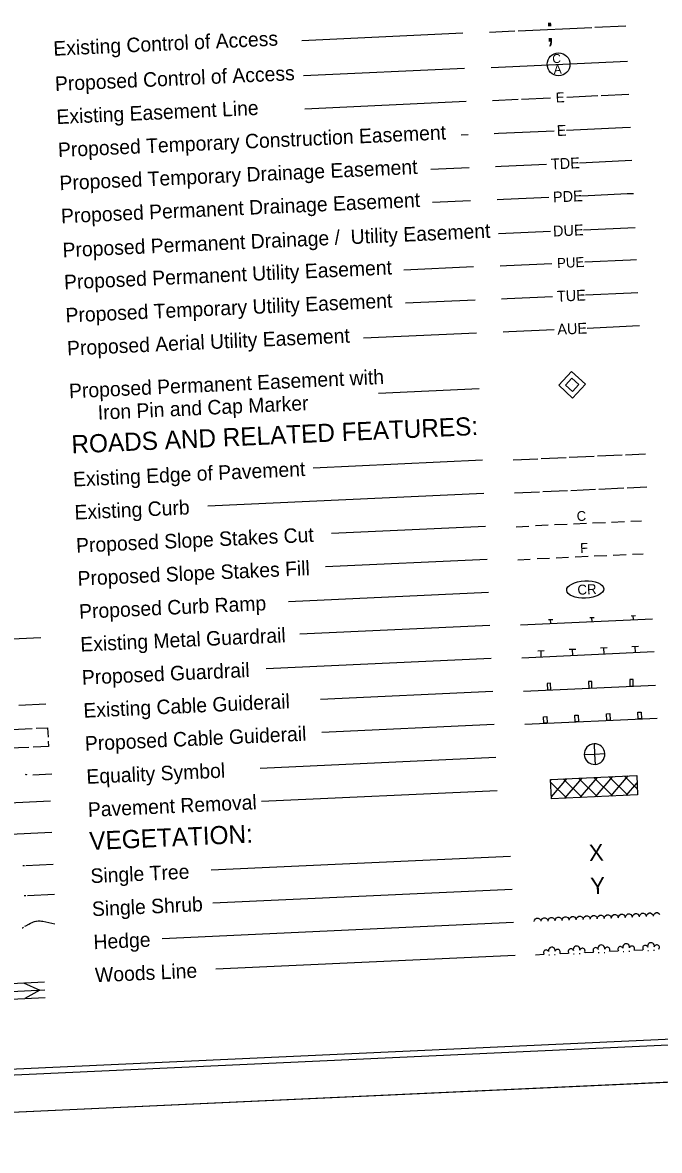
# Model space of a CAD drawing. Extents: x 1190067 to 1192950, y 891516 to 893460.
# Drawn here: x 1191359.1 to 1191513.1, y 891516.5 to 891789.2 of the extents above; entities that cross this region are included whole.
import ezdxf

# ---------------------------------------------------------------- set-up
doc = ezdxf.new("R2010")
doc.units = 0
for name, color, linetype in [('Prop Dimension Text', 7, 'Continuous'), ('Prop Easement Permanent Drainage Utility', 7, 'Continuous'), ('Prop ROW Permanent Easement CELL', 7, 'Continuous'), ('Prop WCC CELL', 7, 'Continuous'), ('Sheet Cutting Line CELL', 7, 'Continuous'), ('Sheet Plot Border Inside CELL', 7, 'Continuous'), ('Sheet Plot Border Outside CELL', 7, 'Continuous'), ('Sheet Symbology CELL', 7, 'Continuous')]:
    doc.layers.add(name, color=color, linetype=linetype)

# ---------------------------------------------------------------- blocks, each defined once
blk = doc.blocks.new('EQCIR')
at = {"layer": 'Sheet Symbology CELL'}
for p, q in [((-0.25, 0), (0, 0)), ((0, 0.25), (0, 0)), ((0, 0), (0, -0.25)), ((0, 0), (0.25, 0))]:
    blk.add_line(p, q, dxfattribs=at)
for start, end in [(89.9944, 179.9989), (359.9944, 89.9989), (179.9944, 269.9989), (269.9944, 359.9989)]:
    blk.add_arc((0, 0), 0.25, start, end, dxfattribs=at)
blk = doc.blocks.new('ROW Marker Permanent Easement-E')
at = {"layer": 'Prop ROW Permanent Easement CELL'}
blk.add_line((0, 0), (0, 0), dxfattribs=at)
for points in [[(0, 0.072), (0.072, 0), (0, -0.072), (-0.072, 0)], [(0, 0.036), (0.036, 0), (0, -0.036), (-0.036, 0)]]:
    blk.add_lwpolyline(points, close=True, dxfattribs=at)
blk = doc.blocks.new('CR')
at = {"layer": 'Prop WCC CELL'}
blk.add_ellipse((0.02, -0.02), major_axis=(5.61, 0), ratio=0.462467, dxfattribs=at)
blk.add_text('CR', height=3, dxfattribs=at).set_placement((-2.34, -1.5))

msp = doc.modelspace()

# ---------------------------------------------------------------- linework, layer by layer
at = {"layer": 'Prop Easement Permanent Drainage Utility'}
for p, q in [((1191474.24, 891738.12), (1191486.75, 891738.7)), ((1191494.74, 891739.06), (1191507.21, 891739.63))]:
    msp.add_line(p, q, dxfattribs=at)
at = {"layer": 'Sheet Cutting Line CELL'}
msp.add_line((1191153.84, 891516.49), (1191826.73, 891547.27), dxfattribs=at)
at = {"layer": 'Sheet Plot Border Inside CELL'}
msp.add_lwpolyline([(1191158.62, 891525.69), (1191824.52, 891556.16), (1191805.24, 891977.76), (1191139.33, 891947.29)], close=True, dxfattribs=at)
at = {"layer": 'Sheet Plot Border Outside CELL'}
msp.add_lwpolyline([(1191153.84, 891516.49), (1191826.73, 891547.27), (1191806.62, 891986.81), (1191133.73, 891956.03)], close=True, dxfattribs=at)
at = {"layer": 'Sheet Symbology CELL'}
for p, q in [((1191478.99, 891787.17), (1191496.74, 891787.98)), ((1191497.53, 891788.01), (1191504.98, 891788.35)), ((1191465.61, 891786.55), (1191426.63, 891784.77)), ((1191472.01, 891786.85), (1191478.19, 891787.13)), ((1191472.4, 891778.31), (1191505.37, 891779.82)), ((1191466, 891778.02), (1191427.02, 891776.24)), ((1191490.75, 891771.15), (1191498.25, 891771.49)), ((1191499.05, 891771.53), (1191505.73, 891771.83)), ((1191466.36, 891770.03), (1191427.38, 891768.25)), ((1191472.77, 891770.32), (1191478.97, 891770.61)), ((1191479.77, 891770.64), (1191486.76, 891770.96)), ((1191474.18, 891762.38), (1191487.66, 891763)), ((1191490.66, 891763.13), (1191504.15, 891763.75)), ((1191504.15, 891763.75), (1191506.1, 891763.84)), ((1191466.88, 891762.05), (1191465.21, 891761.97)), ((1191473.13, 891762.33), (1191474.18, 891762.38)), ((1191474.84, 891754.4), (1191485.83, 891754.9)), ((1191493.82, 891755.27), (1191504.81, 891755.77)), ((1191504.81, 891755.77), (1191506.46, 891755.85)), ((1191467.09, 891754.05), (1191457.84, 891753.62)), ((1191473.5, 891754.34), (1191474.84, 891754.4)), ((1191475.38, 891746.42), (1191486.37, 891746.92)), ((1191494.36, 891747.29), (1191505.35, 891747.79)), ((1191505.35, 891747.79), (1191506.83, 891747.86)), ((1191467.46, 891746.06), (1191458.21, 891745.63)), ((1191473.86, 891746.35), (1191475.38, 891746.42)), ((1191474.6, 891730.36), (1191476.13, 891730.43)), ((1191476.13, 891730.43), (1191487.12, 891730.93)), ((1191495.11, 891731.3), (1191506.1, 891731.8)), ((1191506.1, 891731.8), (1191507.56, 891731.87)), ((1191468.19, 891730.07), (1191451.35, 891729.3)), ((1191468.56, 891722.08), (1191451.72, 891721.31)), ((1191474.96, 891722.37), (1191476.3, 891722.43)), ((1191476.3, 891722.43), (1191487.29, 891722.93)), ((1191495.28, 891723.3), (1191506.27, 891723.8)), ((1191506.27, 891723.8), (1191507.93, 891723.88)), ((1191468.92, 891714.09), (1191441.57, 891712.83)), ((1191475.33, 891714.38), (1191476.67, 891714.44)), ((1191476.67, 891714.44), (1191487.65, 891714.94)), ((1191495.65, 891715.31), (1191506.63, 891715.81)), ((1191506.63, 891715.81), (1191508.29, 891715.89)), ((1191469.54, 891700.57), (1191445.16, 891699.45)), ((1191484.54, 891683.75), (1191490.53, 891684.02)), ((1191491.33, 891684.06), (1191497.32, 891684.33)), ((1191498.12, 891684.37), (1191504.12, 891684.64)), ((1191504.92, 891684.68), (1191509.71, 891684.9)), ((1191470.33, 891683.33), (1191429.43, 891681.45)), ((1191477.74, 891683.43), (1191483.74, 891683.71)), ((1191478.11, 891675.44), (1191484.1, 891675.72)), ((1191484.9, 891675.75), (1191490.9, 891676.03)), ((1191491.7, 891676.06), (1191497.69, 891676.34)), ((1191498.49, 891676.38), (1191504.48, 891676.65)), ((1191505.28, 891676.69), (1191510.08, 891676.91)), ((1191470.69, 891675.33), (1191403.9, 891672.28)), ((1191486.2, 891667.61), (1191483.18, 891667.48)), ((1191490.79, 891667.82), (1191487.75, 891667.69)), ((1191495.49, 891668.04), (1191492.37, 891667.9)), ((1191500.06, 891668.25), (1191496.96, 891668.11)), ((1191504.68, 891668.46), (1191501.54, 891668.32)), ((1191508.79, 891668.65), (1191506.23, 891668.53)), ((1191471.06, 891667.34), (1191433.82, 891665.64)), ((1191478.48, 891667.26), (1191481.52, 891667.4)), ((1191471.43, 891659.35), (1191432.37, 891657.56)), ((1191478.85, 891659.27), (1191481.89, 891659.41)), ((1191486.56, 891659.62), (1191483.54, 891659.48)), ((1191491.16, 891659.83), (1191488.12, 891659.69)), ((1191495.85, 891660.05), (1191492.73, 891659.9)), ((1191500.43, 891660.26), (1191497.33, 891660.12)), ((1191505.04, 891660.47), (1191501.91, 891660.32)), ((1191509.16, 891660.66), (1191506.6, 891660.54)), ((1191471.79, 891651.36), (1191423.47, 891649.15)), ((1191506.29, 891645.75), (1191507.29, 891645.79)), ((1191506.83, 891644.77), (1191506.79, 891645.77)), ((1191472.09, 891643.41), (1191426.21, 891641.31)), ((1191479.51, 891643.52), (1191511.47, 891644.98)), ((1191486.31, 891644.83), (1191487.31, 891644.88)), ((1191486.85, 891643.86), (1191486.81, 891644.86)), ((1191496.3, 891645.29), (1191497.3, 891645.34)), ((1191496.84, 891644.31), (1191496.8, 891645.31)), ((1191331.62, 891639), (1191363.58, 891640.46)), ((1191491.28, 891637.63), (1191492.88, 891637.71)), ((1191492.15, 891636.09), (1191492.08, 891637.67)), ((1191498.87, 891637.98), (1191500.47, 891638.05)), ((1191499.74, 891636.44), (1191499.67, 891638.02)), ((1191506.46, 891638.33), (1191508.06, 891638.4)), ((1191507.33, 891636.79), (1191507.26, 891638.36)), ((1191472.46, 891635.42), (1191418.02, 891632.93)), ((1191511.84, 891636.99), (1191479.87, 891635.53)), ((1191483.69, 891637.29), (1191485.28, 891637.36)), ((1191484.56, 891635.74), (1191484.49, 891637.32)), ((1191472.82, 891627.43), (1191431.15, 891625.52)), ((1191480.24, 891627.54), (1191512.2, 891629)), ((1191358.19, 891624.12), (1191364.77, 891624.42)), ((1191356.47, 891618.27), (1191361.47, 891618.5)), ((1191473.19, 891619.44), (1191431.51, 891617.53)), ((1191480.6, 891619.55), (1191512.57, 891621.01)), ((1191360.66, 891613.93), (1191355.67, 891613.7)), ((1191473.55, 891611.45), (1191416.56, 891608.84)), ((1191486.8, 891606.16), (1191507.62, 891607.11)), ((1191487.02, 891601.49), (1191486.8, 891606.16)), ((1191486.81, 891605.92), (1191487.02, 891606.17)), ((1191490.71, 891601.65), (1191486.84, 891605.44)), ((1191487, 891601.95), (1191490.74, 891606.34)), ((1191494.43, 891601.82), (1191489.82, 891606.3)), ((1191490.27, 891601.63), (1191494.45, 891606.51)), ((1191498.12, 891601.99), (1191493.54, 891606.47)), ((1191493.97, 891601.8), (1191498.17, 891606.68)), ((1191501.84, 891602.16), (1191497.23, 891606.64)), ((1191497.68, 891601.97), (1191501.87, 891606.85)), ((1191505.56, 891602.33), (1191500.93, 891606.81)), ((1191501.4, 891602.14), (1191505.56, 891607.02)), ((1191507.77, 891603.94), (1191504.64, 891606.98)), ((1191505.1, 891602.31), (1191507.7, 891605.35)), ((1191507.62, 891607.11), (1191507.83, 891602.44)), ((1191473.92, 891603.45), (1191416.93, 891600.85)), ((1191507.83, 891602.44), (1191487.02, 891601.49)), ((1191365.85, 891600.94), (1191354.14, 891600.4)), ((1191366.19, 891593.35), (1191354.48, 891592.82)), ((1191359.96, 891585.38), (1191366.55, 891585.68)), ((1191477.11, 891587.56), (1191404.73, 891584.24)), ((1191359.16, 891585.35), (1191359.56, 891585.36)), ((1191359.49, 891578.11), (1191359.89, 891578.12)), ((1191360.29, 891578.14), (1191366.88, 891578.44)), ((1191477.47, 891579.56), (1191405.1, 891576.25)), ((1191482.79, 891571.8), (1191482.89, 891572.18)), ((1191482.89, 891572.18), (1191483.12, 891572.45)), ((1191483.12, 891572.45), (1191483.43, 891572.65)), ((1191483.43, 891572.65), (1191483.81, 891572.67)), ((1191483.81, 891572.67), (1191484.14, 891572.48)), ((1191484.14, 891572.48), (1191484.37, 891572.23)), ((1191484.37, 891572.23), (1191484.47, 891571.9)), ((1191484.49, 891571.88), (1191484.59, 891572.26)), ((1191484.59, 891572.26), (1191484.82, 891572.53)), ((1191484.82, 891572.53), (1191485.13, 891572.73)), ((1191485.13, 891572.73), (1191485.51, 891572.74)), ((1191485.51, 891572.74), (1191485.84, 891572.56)), ((1191485.84, 891572.56), (1191486.07, 891572.31)), ((1191486.07, 891572.31), (1191486.16, 891571.97)), ((1191486.18, 891571.95), (1191486.29, 891572.34)), ((1191486.29, 891572.34), (1191486.52, 891572.61)), ((1191486.52, 891572.61), (1191486.83, 891572.8)), ((1191486.83, 891572.8), (1191487.21, 891572.82)), ((1191487.21, 891572.82), (1191487.54, 891572.64)), ((1191487.54, 891572.64), (1191487.77, 891572.39)), ((1191487.77, 891572.39), (1191487.86, 891572.05)), ((1191487.88, 891572.03), (1191487.99, 891572.42)), ((1191487.99, 891572.42), (1191488.21, 891572.69)), ((1191488.21, 891572.69), (1191488.52, 891572.88)), ((1191488.52, 891572.88), (1191488.9, 891572.9)), ((1191488.9, 891572.9), (1191489.23, 891572.71)), ((1191489.23, 891572.71), (1191489.47, 891572.46)), ((1191489.47, 891572.46), (1191489.56, 891572.13)), ((1191489.58, 891572.11), (1191489.68, 891572.49)), ((1191489.68, 891572.49), (1191489.91, 891572.77)), ((1191489.91, 891572.77), (1191490.22, 891572.96)), ((1191490.22, 891572.96), (1191490.6, 891572.98)), ((1191490.6, 891572.98), (1191490.93, 891572.79)), ((1191490.93, 891572.79), (1191491.16, 891572.54)), ((1191491.16, 891572.54), (1191491.26, 891572.21)), ((1191491.28, 891572.19), (1191491.38, 891572.57)), ((1191491.38, 891572.57), (1191491.61, 891572.84)), ((1191491.61, 891572.84), (1191491.92, 891573.04)), ((1191491.92, 891573.04), (1191492.3, 891573.05)), ((1191492.3, 891573.05), (1191492.63, 891572.87)), ((1191492.63, 891572.87), (1191492.86, 891572.62)), ((1191492.86, 891572.62), (1191492.96, 891572.28)), ((1191492.98, 891572.26), (1191493.08, 891572.65)), ((1191493.08, 891572.65), (1191493.31, 891572.92)), ((1191493.31, 891572.92), (1191493.62, 891573.11)), ((1191493.62, 891573.11), (1191494, 891573.13)), ((1191494, 891573.13), (1191494.33, 891572.95)), ((1191494.33, 891572.95), (1191494.56, 891572.7)), ((1191494.56, 891572.7), (1191494.66, 891572.36)), ((1191494.68, 891572.34), (1191494.78, 891572.73)), ((1191494.78, 891572.73), (1191495.01, 891573)), ((1191495.01, 891573), (1191495.32, 891573.19)), ((1191495.32, 891573.19), (1191495.7, 891573.21)), ((1191495.7, 891573.21), (1191496.03, 891573.02)), ((1191496.03, 891573.02), (1191496.26, 891572.78)), ((1191496.26, 891572.78), (1191496.35, 891572.44)), ((1191496.37, 891572.42), (1191496.48, 891572.81)), ((1191496.48, 891572.81), (1191496.7, 891573.08)), ((1191496.7, 891573.08), (1191497.02, 891573.27)), ((1191497.02, 891573.27), (1191497.4, 891573.29)), ((1191497.4, 891573.29), (1191497.72, 891573.1)), ((1191497.72, 891573.1), (1191497.96, 891572.85)), ((1191497.96, 891572.85), (1191498.05, 891572.52)), ((1191498.07, 891572.5), (1191498.18, 891572.88)), ((1191498.18, 891572.88), (1191498.4, 891573.15)), ((1191498.4, 891573.15), (1191498.71, 891573.35)), ((1191498.71, 891573.35), (1191499.09, 891573.37)), ((1191499.09, 891573.37), (1191499.42, 891573.18)), ((1191499.42, 891573.18), (1191499.65, 891572.93)), ((1191499.65, 891572.93), (1191499.75, 891572.59)), ((1191499.77, 891572.58), (1191499.87, 891572.96)), ((1191499.87, 891572.96), (1191500.1, 891573.23)), ((1191500.1, 891573.23), (1191500.41, 891573.43)), ((1191500.41, 891573.43), (1191500.79, 891573.44)), ((1191500.79, 891573.44), (1191501.12, 891573.26)), ((1191501.12, 891573.26), (1191501.35, 891573.01)), ((1191501.35, 891573.01), (1191501.45, 891572.67)), ((1191501.47, 891572.65), (1191501.57, 891573.04)), ((1191501.57, 891573.04), (1191501.8, 891573.31)), ((1191501.8, 891573.31), (1191502.11, 891573.5)), ((1191502.11, 891573.5), (1191502.49, 891573.52)), ((1191502.49, 891573.52), (1191502.82, 891573.34)), ((1191502.82, 891573.34), (1191503.05, 891573.09)), ((1191503.05, 891573.09), (1191503.15, 891572.75)), ((1191503.17, 891572.73), (1191503.27, 891573.12)), ((1191503.27, 891573.12), (1191503.5, 891573.39)), ((1191503.5, 891573.39), (1191503.81, 891573.58)), ((1191503.81, 891573.58), (1191504.19, 891573.6)), ((1191504.19, 891573.6), (1191504.52, 891573.41)), ((1191504.52, 891573.41), (1191504.75, 891573.16)), ((1191504.75, 891573.16), (1191504.84, 891572.83)), ((1191504.87, 891572.81), (1191504.97, 891573.19)), ((1191504.97, 891573.19), (1191505.2, 891573.46)), ((1191505.2, 891573.46), (1191505.51, 891573.66)), ((1191505.51, 891573.66), (1191505.89, 891573.68)), ((1191505.89, 891573.68), (1191506.22, 891573.49)), ((1191506.22, 891573.49), (1191506.45, 891573.24)), ((1191506.45, 891573.24), (1191506.54, 891572.91)), ((1191506.56, 891572.89), (1191506.67, 891573.27)), ((1191506.67, 891573.27), (1191506.89, 891573.54)), ((1191506.89, 891573.54), (1191507.21, 891573.74)), ((1191507.21, 891573.74), (1191507.59, 891573.75)), ((1191507.59, 891573.75), (1191507.91, 891573.57)), ((1191507.91, 891573.57), (1191508.15, 891573.32)), ((1191508.15, 891573.32), (1191508.24, 891572.98)), ((1191508.26, 891572.96), (1191508.36, 891573.35)), ((1191508.36, 891573.35), (1191508.59, 891573.62)), ((1191508.59, 891573.62), (1191508.9, 891573.81)), ((1191508.9, 891573.81), (1191509.28, 891573.83)), ((1191509.28, 891573.83), (1191509.61, 891573.65)), ((1191509.61, 891573.65), (1191509.84, 891573.4)), ((1191509.84, 891573.4), (1191509.94, 891573.06)), ((1191509.96, 891573.04), (1191510.06, 891573.43)), ((1191510.06, 891573.43), (1191510.29, 891573.7)), ((1191510.29, 891573.7), (1191510.6, 891573.89)), ((1191510.6, 891573.89), (1191510.98, 891573.91)), ((1191510.98, 891573.91), (1191511.31, 891573.72)), ((1191511.31, 891573.72), (1191511.54, 891573.47)), ((1191511.54, 891573.47), (1191511.64, 891573.14)), ((1191511.66, 891573.12), (1191511.76, 891573.5)), ((1191511.76, 891573.5), (1191511.99, 891573.78)), ((1191511.99, 891573.78), (1191512.3, 891573.97)), ((1191512.3, 891573.97), (1191512.68, 891573.99)), ((1191512.68, 891573.99), (1191513.01, 891573.8)), ((1191513.01, 891573.8), (1191513.24, 891573.55)), ((1191477.84, 891571.57), (1191392.85, 891567.68)), ((1191483.15, 891563.81), (1191485.15, 891563.9)), ((1191489.15, 891564.08), (1191491.15, 891564.17)), ((1191492.33, 891564.03), (1191492.53, 891564.04)), ((1191493.73, 891564.09), (1191493.93, 891564.1)), ((1191495.14, 891564.36), (1191497.14, 891564.45)), ((1191498.33, 891564.3), (1191498.53, 891564.31)), ((1191499.73, 891564.36), (1191499.93, 891564.37)), ((1191501.14, 891564.63), (1191503.13, 891564.72)), ((1191504.32, 891564.58), (1191504.52, 891564.58)), ((1191505.72, 891564.64), (1191505.92, 891564.65)), ((1191507.13, 891564.9), (1191509.13, 891565)), ((1191510.31, 891564.85), (1191510.51, 891564.86)), ((1191511.71, 891564.91), (1191511.91, 891564.92)), ((1191478.2, 891563.58), (1191405.83, 891560.27)), ((1191486.34, 891563.75), (1191486.54, 891563.76)), ((1191487.74, 891563.82), (1191487.94, 891563.83)), ((1191340.06, 891556.09), (1191364.44, 891557.21)), ((1191359.36, 891556.98), (1191363.28, 891555.23)), ((1191340.04, 891554.17), (1191364.53, 891555.29)), ((1191340.23, 891552.32), (1191364.61, 891553.43)), ((1191363.28, 891555.23), (1191359.64, 891553.21))]:
    msp.add_line(p, q, dxfattribs=at)
for points in [[(1191800.29, 891976.51), (1191200.91, 891949.09), (1191220.09, 891529.94), (1191819.46, 891557.36)], [(1191486.02, 891627.8), (1191486.82, 891627.84), (1191486.75, 891629.44), (1191485.95, 891629.4)], [(1191496.01, 891628.26), (1191496.81, 891628.3), (1191496.74, 891629.89), (1191495.94, 891629.86)], [(1191506, 891628.72), (1191506.8, 891628.75), (1191506.73, 891630.35), (1191505.93, 891630.31)], [(1191485.11, 891621.35), (1191485.91, 891621.39), (1191485.98, 891619.79), (1191485.18, 891619.76)], [(1191492.7, 891621.7), (1191493.5, 891621.74), (1191493.58, 891620.14), (1191492.78, 891620.1)], [(1191500.3, 891622.05), (1191501.09, 891622.09), (1191501.17, 891620.49), (1191500.37, 891620.45)], [(1191507.89, 891622.4), (1191508.69, 891622.43), (1191508.76, 891620.83), (1191507.96, 891620.8)]]:
    msp.add_lwpolyline(points, close=True, dxfattribs=at)
for points in [[(1191362.46, 891618.54), (1191365.19, 891618.67), (1191365.3, 891616.4)], [(1191365.34, 891615.4), (1191365.4, 891614.14), (1191361.66, 891613.97)], [(1191361.64, 891607.3), (1191366.2, 891607.51)], [(1191359.01, 891570.29), (1191359.08, 891570.33), (1191359.36, 891570.47)], [(1191359.71, 891570.67), (1191359.9, 891570.77), (1191360.67, 891571.22), (1191361.06, 891571.43), (1191361.46, 891571.62), (1191361.77, 891571.74), (1191362.05, 891571.82), (1191362.3, 891571.88), (1191362.52, 891571.93), (1191362.9, 891571.97), (1191363.19, 891571.98), (1191363.41, 891571.98), (1191363.73, 891571.95), (1191364.05, 891571.89), (1191365.48, 891571.57), (1191366.92, 891571.24)]]:
    msp.add_lwpolyline(points, dxfattribs=at)
msp.add_circle((1191488.73, 891779.06), 2.76, dxfattribs=at)
for centre, radius, start, end in [((1191511.07, 891565.89), 0.825, 348.5832, 196.6557), ((1191485.71, 891564.33), 0.632, 21.0544, 221.851), ((1191487.09, 891564.79), 0.825, 348.5832, 196.6557), ((1191488.51, 891564.46), 0.632, 323.3879, 164.1845), ((1191491.71, 891564.6), 0.632, 21.0544, 221.851), ((1191493.09, 891565.07), 0.825, 348.5832, 196.6557), ((1191494.5, 891564.73), 0.632, 323.3879, 164.1845), ((1191497.7, 891564.88), 0.632, 21.0544, 221.851), ((1191499.08, 891565.34), 0.825, 348.5832, 196.6557), ((1191500.5, 891565.01), 0.632, 323.3879, 164.1845), ((1191503.69, 891565.15), 0.632, 21.0544, 221.851), ((1191505.07, 891565.62), 0.825, 348.5832, 196.6557), ((1191506.49, 891565.28), 0.632, 323.3879, 164.1845), ((1191509.69, 891565.43), 0.632, 21.0544, 221.851), ((1191512.48, 891565.56), 0.632, 323.3879, 164.1845)]:
    msp.add_arc(centre, radius, start, end, dxfattribs=at)
msp.add_ellipse((1191359.99, 891607.34), major_axis=(-0.0036, 0.0787), ratio=0.938496, dxfattribs=at)

# ---------------------------------------------------------------- block references
at = {"layer": 'Prop Dimension Text'}
for name, p, xscale, yscale, rotation in [('ROW Marker Permanent Easement-E', (1191491.99, 891701.6), 44.73509307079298, 44.73509307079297, 2.6194666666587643), ('CR', (1191495.16, 891652.1), 0.8000000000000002, 0.7999999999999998, 2.6194666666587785), ('EQCIR', (1191497.44, 891612.3), 10.000000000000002, 10, 2.619466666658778)]:
    msp.add_blockref(name, p, dxfattribs=dict(at, xscale=xscale, yscale=yscale, rotation=rotation))

# ---------------------------------------------------------------- texts
at = {"layer": 'Prop Easement Permanent Drainage Utility'}
msp.add_text('DUE', height=2.62, rotation=2.6195, dxfattribs=at).set_placement((1191487.44, 891737.41))
at = {"layer": 'Sheet Symbology CELL'}
for s, height, p in [(';', 6, (1191485.63, 891784.47)), ('Existing Control of Access', 3.5, (1191366.65, 891781.12)), ('C', 2.16, (1191487.26, 891779.32)), ('Proposed Control of Access', 3.5, (1191367.04, 891772.59)), ('A', 2.16, (1191487.59, 891776.74)), ('E', 2.4, (1191488.09, 891769.82)), ('Existing Easement Line', 3.5, (1191367.41, 891764.6)), ('Proposed Temporary Construction Easement', 3.5, (1191367.77, 891756.61)), ('E', 2.62, (1191488.36, 891761.71)), ('Proposed Temporary Drainage Easement', 3.5, (1191368.14, 891748.61)), ('TDE', 2.62, (1191486.93, 891753.63)), ('Proposed Permanent Drainage Easement', 3.5, (1191368.5, 891740.62)), ('PDE', 2.62, (1191487.43, 891745.65)), ('Proposed Permanent Drainage /  Utility Easement', 3.5, (1191368.88, 891732.4)), ('Proposed Permanent Utility Easement', 3.5, (1191369.24, 891724.64)), ('PUE', 2.4, (1191488.41, 891729.79)), ('Proposed Temporary Utility Easement', 3.5, (1191369.6, 891716.64)), ('TUE', 2.62, (1191488.38, 891721.66)), ('AUE', 2.62, (1191488.48, 891713.66)), ('Proposed Aerial Utility Easement', 3.5, (1191369.97, 891708.65)), ('Proposed Permanent Easement with', 3.5, (1191370.44, 891698.32)), ('Iron Pin and Cap Marker', 3.5, (1191377.39, 891693.13)), ('ROADS AND RELATED FEATURES:', 4.4, (1191371.05, 891684.97)), ('Existing Edge of Pavement', 3.5, (1191371.42, 891676.98)), ('Existing Curb', 3.5, (1191371.78, 891668.99)), ('C', 2.37, (1191493.16, 891668.63)), ('Proposed Slope Stakes Cut', 3.5, (1191372.15, 891660.99)), ('F', 2.37, (1191493.99, 891660.91)), ('Proposed Slope Stakes Fill', 3.5, (1191372.51, 891653)), ('Proposed Curb Ramp', 3.5, (1191372.88, 891645.01)), ('Existing Metal Guardrail', 3.5, (1191373.18, 891637.07)), ('Proposed Guardrail', 3.5, (1191373.55, 891629.08)), ('Existing Cable Guiderail', 3.5, (1191373.92, 891621.09)), ('Proposed Cable Guiderail', 3.5, (1191374.28, 891613.1)), ('Equality Symbol', 3.5, (1191374.65, 891605.1)), ('Pavement Removal', 3.5, (1191375.01, 891597.11)), ('VEGETATION:', 4.4, (1191375.37, 891589.09)), ('X', 4, (1191496.13, 891586.42)), ('Single Tree', 3.5, (1191375.63, 891581.1)), ('Y', 4, (1191496.5, 891578.43)), ('Single Shrub', 3.5, (1191375.99, 891573.11)), ('Hedge', 3.5, (1191376.36, 891565.12)), ('Woods Line', 3.5, (1191376.73, 891557.13))]:
    msp.add_text(s, height=height, rotation=2.6195, dxfattribs=at).set_placement(p)

doc.saveas('drawing.dxf')
